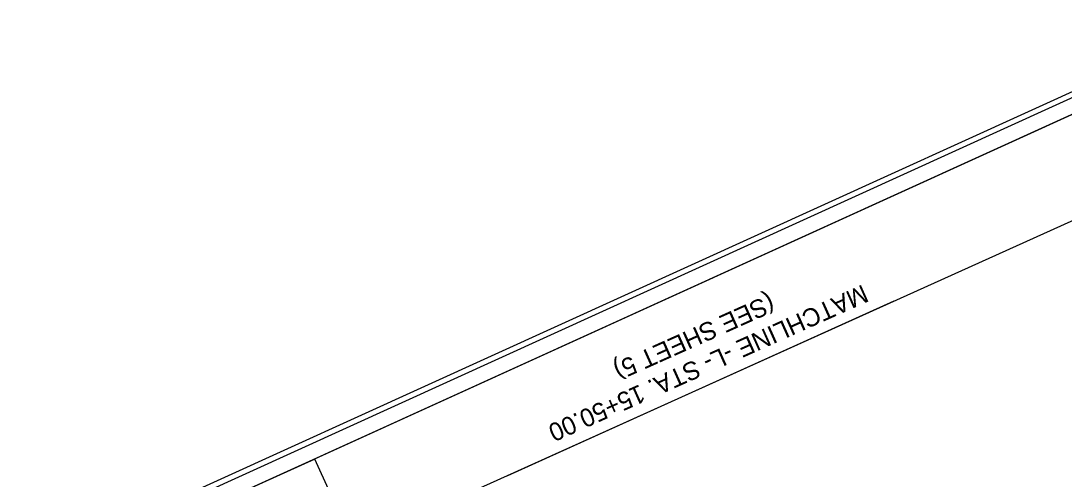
# Model space of a CAD drawing. Extents: x 2097293 to 2098987, y 683915 to 685901.
# Drawn here: x 2097293 to 2098154, y 685522 to 685901 of the extents above; entities that cross this region are included whole.
import ezdxf

# ---------------------------------------------------------------- set-up
doc = ezdxf.new("R2010")
doc.units = 0
for name, color, linetype in [('Matchline', 7, 'Continuous'), ('Matchline Text', 7, 'Continuous'), ('Scratch_Level_6', 7, 'Continuous'), ('Sheet Layout Plan Border', 7, 'Continuous'), ('Sheet Plan CELL', 7, 'Continuous'), ('Sheet Plot Border Inside CELL', 7, 'Continuous'), ('Sheet Plot Border Outside CELL', 7, 'Continuous')]:
    doc.layers.add(name, color=color, linetype=linetype)

msp = doc.modelspace()

# ---------------------------------------------------------------- linework, layer by layer
at = {"layer": 'Matchline'}
msp.add_line((2097694.69, 685525.59), (2098013.7, 685669.59), dxfattribs=at)
at = {"layer": 'Scratch_Level_6'}
msp.add_lwpolyline([(2097480.76, 685514.24), (2097563.62, 685332.14), (2097618.23, 685357), (2097535.37, 685539.09)], close=True, dxfattribs=at)
at = {"layer": 'Sheet Layout Plan Border'}
for points in [[(2098897.26, 684510.8), (2097941.56, 684075.89), (2097486.05, 685076.91), (2097476.37, 685098.19), (2097403.15, 685259.11), (2097618.23, 685357), (2097567.61, 685468.23), (2098309.25, 685803.01)], [(2098897.26, 684510.8), (2097941.56, 684075.89), (2097486.05, 685076.91), (2097476.38, 685098.16), (2097403.15, 685259.11), (2097618.23, 685357), (2097567.61, 685468.23), (2098309.25, 685803.01)]]:
    msp.add_lwpolyline(points, close=True, dxfattribs=at)
at = {"layer": 'Sheet Plan CELL'}
for points in [[(2097320.28, 685441.22), (2097941.56, 684075.89), (2098897.27, 684510.77), (2098276, 685876.08)], [(2098897.27, 684510.77), (2097941.59, 684075.88), (2097403.14, 685259.11), (2097539.72, 685321.27), (2097456.88, 685503.35), (2098276, 685876.08)]]:
    msp.add_lwpolyline(points, close=True, dxfattribs=at)
at = {"layer": 'Sheet Plot Border Inside CELL'}
msp.add_lwpolyline([(2098963.13, 684372.11), (2098273.1, 685888.48), (2097312.85, 685451.54), (2098002.87, 683935.16)], close=True, dxfattribs=at)
at = {"layer": 'Sheet Plot Border Outside CELL'}
msp.add_lwpolyline([(2098986.71, 684368.56), (2098289.45, 685900.88), (2097292.78, 685447.36), (2097990.05, 683915.04)], close=True, dxfattribs=at)

# ---------------------------------------------------------------- texts
at = {"layer": 'Matchline Text'}
for s, p in [('MATCHLINE -L- STA. 15+50.00', (2097987.84, 685683.47)), ('(SEE SHEET 5)', (2097910.9, 685675.73))]:
    msp.add_text(s, height=15, rotation=204.12202, dxfattribs=at).set_placement(p)

doc.saveas('drawing.dxf')
